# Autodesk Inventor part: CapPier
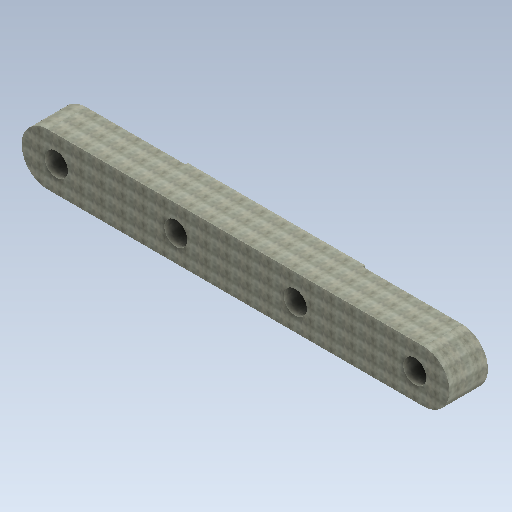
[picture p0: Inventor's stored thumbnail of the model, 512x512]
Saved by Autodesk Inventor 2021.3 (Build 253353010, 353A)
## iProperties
Created: 2021-11
Part Number: CapPier
Material: Concrete, Cast-in-Place, Gray
Document SubType Name: Modeling
Designer: u1426
Density: 2.40731 g/cm^3
Appearance: Flat - Gray 1
Author: u1426
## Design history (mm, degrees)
sketch "Sketch1"
  geometry: L1 (-4953, 685.8)-(4953, 685.8); L2 (5638.8, 0)-(5638.8, 0); L3 (4953, -685.8)-(-4953, -685.8); L4 (-5638.8, 0)-(-5638.8, 0); A1 r 685.8 centre (-4953, 0) between (-4953, 685.8) and (-5638.8, 0); A2 r 685.8 centre (-4953, 0) between (-5638.8, 0) and (-4953, -685.8); A3 r 685.8 centre (4953, 0) between (4953, -685.8) and (5638.8, 0); A4 r 685.8 centre (4953, 0) between (5638.8, 0) and (4953, 685.8); 3 further points
  constraints: 8 end point, 8 point on circle, 8 tangent, 4 centre point, 3 equal radius, 2 parallel, 1 horizontal, 1 perpendicular
  dimensions: "d0" = 5638.8 distance from line of point (0, 0) L4; "d1" = 5638.8 distance from line of point (0, 0) L2; "d2" = 685.8 distance from line of L3 point (0, 0); "d3" = 685.8 distance from line of point (0, 0) L1; "d4" = 685.8 radius of A1
extrude "Extrusion1" new body sketch "Sketch1" distance "d5" = 1016; taper "d6" = 0 deg
sketch "Sketch2"
  geometry: 5 further points
  dimensions: "d14" = 0 vertical distance of point (-4724.4, 0) point (0, 0); "d15" = 1574.8 distance of point (-1574.8, 0) point (0, 0); "d16" = 3149.6 distance of point (-4724.4, 0) point (-1574.8, 0); "d17" = 1574.8 distance of point (1574.8, 0) point (0, 0); "d18" = 3149.6 distance of point (4724.4, 0) point (1574.8, 0); "d19" = 0 vertical distance of point (1574.8, 0) point (0, 0); "d20" = 0 vertical distance of point (4724.4, 0) point (0, 0); "d21" = 0 vertical distance of point (-1574.8, 0) point (0, 0)
hole "Hole1" sketch "Sketch2" at (-4724.4, 0), (-1574.8, 0), (1574.8, 0), (4724.4, 0) diameter "d7" = 609.6; stored, may be unused: countersink angle "d11" = 82 deg, drill point angle "d13" = 0 deg; dims "d8" = 19.05, "d9" = 9.525, "d10" = 6.35, "d12" = 508
sketch "Sketch3"
  geometry: L1 (0, 1016)-(9906, 1016) reference; L2 (2616.2, 1016)-(7289.8, 1016); L3 (7289.8, 1016)-(7289.8, 1080.008); L4 (7289.8, 1080.008)-(2616.2, 1080.008); L5 (2616.2, 1080.008)-(2616.2, 1016); 2 further points
  constraints: 8 end point, 2 parallel, 1 horizontal, 1 perpendicular, 1 point on line
  dimensions: "d22" = 2336.8 distance from line of point (4953, 0) L5; "d23" = 2336.8 distance from line of point (4953, 0) L3; "d24" = 64.008 distance of L2.end L3.end
extrude "Extrusion2" join sketch "Sketch3" stored distance "d25" = 1016; taper "d26" = 0 deg
body "Solid1"
